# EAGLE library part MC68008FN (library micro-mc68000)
68xxx PROCESSOR
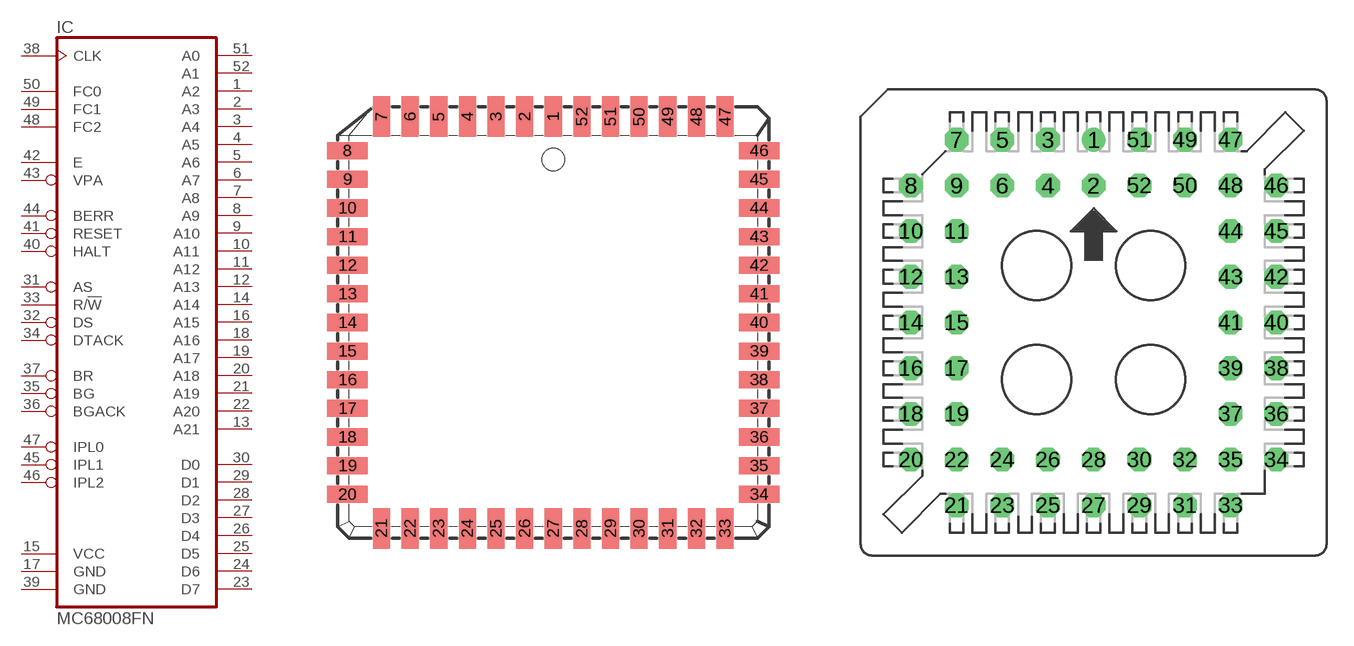
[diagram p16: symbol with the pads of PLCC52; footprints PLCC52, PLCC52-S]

Designator prefix IC

## MC68008FN (OC_FARNELL: unknown; OC_NEWARK: unknown)  [PLCC52]
1  A2  out
2  A3  out
3  A4  out
4  A5  out
5  A6  out
6  A7  out
7  A8  out
8  A9  out
9  A10  out
10  A11  out
11  A12  out
12  A13  out
13  A21  out
14  A14  out
15  VCC  pwr
16  A15  out
17  GND  pwr
18  A16  out
19  A17  out
20  A18  out
21  A19  out
22  A20  out
23  D7
24  D6
25  D5
26  D4
27  D3
28  D2
29  D1
30  D0
31  AS  out
32  DS  out
33  R/!W  out
34  DTACK  in
35  BG  out
36  BGACK  in
37  BR  in
38  CLK  in
39  GND  pwr
40  HALT
41  RESET
42  E  out
43  VPA  in
44  BERR  in
45  IPL1  in
46  IPL2  in
47  IPL0  in
48  FC2  out
49  FC1  out
50  FC0  out
51  A0  out
52  A1  out

## MC68008FN-SOC (OC_FARNELL: unknown; OC_NEWARK: unknown)  [PLCC52-S]
Pads as for PLCC52

## Footprint PLCC52 (pad centres in mm)
PLASTIC LEADED CHIP CARRIER square
smd 0.76 x 1.8: 1 0,9.13; 2 -1.27,9.13; 3 -2.54,9.13; 4 -3.81,9.13; 5 -5.08,9.13; 6 -6.35,9.13; 7 -7.62,9.13; 21 -7.62,-9.13; 22 -6.35,-9.13; 23 -5.08,-9.13; 24 -3.81,-9.13; 25 -2.54,-9.13; 26 -1.27,-9.13; 27 0,-9.13; 28 1.27,-9.13; 29 2.54,-9.13; 30 3.81,-9.13; 31 5.08,-9.13; 32 6.35,-9.13; 33 7.62,-9.13; 47 7.62,9.13; 48 6.35,9.13; 49 5.08,9.13; 50 3.81,9.13; 51 2.54,9.13; 52 1.27,9.13
smd 1.8 x 0.76: 8 -9.13,7.62; 9 -9.13,6.35; 10 -9.13,5.08; 11 -9.13,3.81; 12 -9.13,2.54; 13 -9.13,1.27; 14 -9.13,0; 15 -9.13,-1.27; 16 -9.13,-2.54; 17 -9.13,-3.81; 18 -9.13,-5.08; 19 -9.13,-6.35; 20 -9.13,-7.62; 34 9.13,-7.62; 35 9.13,-6.35; 36 9.13,-5.08; 37 9.13,-3.81; 38 9.13,-2.54; 39 9.13,-1.27; 40 9.13,0; 41 9.13,1.27; 42 9.13,2.54; 43 9.13,3.81; 44 9.13,5.08; 45 9.13,6.35; 46 9.13,7.62

## Footprint PLCC52-S (pad centres in mm)
PLCC Socked
drill 0.813 round: 1 0,10.16
drill 0.813 octagon: 2 0,7.62; 3 -2.54,10.16; 4 -2.54,7.62; 5 -5.08,10.16; 6 -5.08,7.62; 7 -7.62,10.16; 8 -10.16,7.62; 9 -7.62,7.62; 10 -10.16,5.08; 11 -7.62,5.08; 12 -10.16,2.54; 13 -7.62,2.54; 14 -10.16,0; 15 -7.62,0; 16 -10.16,-2.54; 17 -7.62,-2.54; 18 -10.16,-5.08; 19 -7.62,-5.08; 20 -10.16,-7.62; 21 -7.62,-10.16; 22 -7.62,-7.62; 23 -5.08,-10.16; 24 -5.08,-7.62; 25 -2.54,-10.16; 26 -2.54,-7.62; 27 0,-10.16; 28 0,-7.62; 29 2.54,-10.16; 30 2.54,-7.62; 31 5.08,-10.16; 32 5.08,-7.62; 33 7.62,-10.16; 34 10.16,-7.62; 35 7.62,-7.62; 36 10.16,-5.08; 37 7.62,-5.08; 38 10.16,-2.54; 39 7.62,-2.54; 40 10.16,0; 41 7.62,0; 42 10.16,2.54; 43 7.62,2.54; 44 7.62,5.08; 45 10.16,5.08; 46 10.16,7.62; 47 7.62,10.16; 48 7.62,7.62; 49 5.08,10.16; 50 5.08,7.62; 51 2.54,10.16; 52 2.54,7.62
